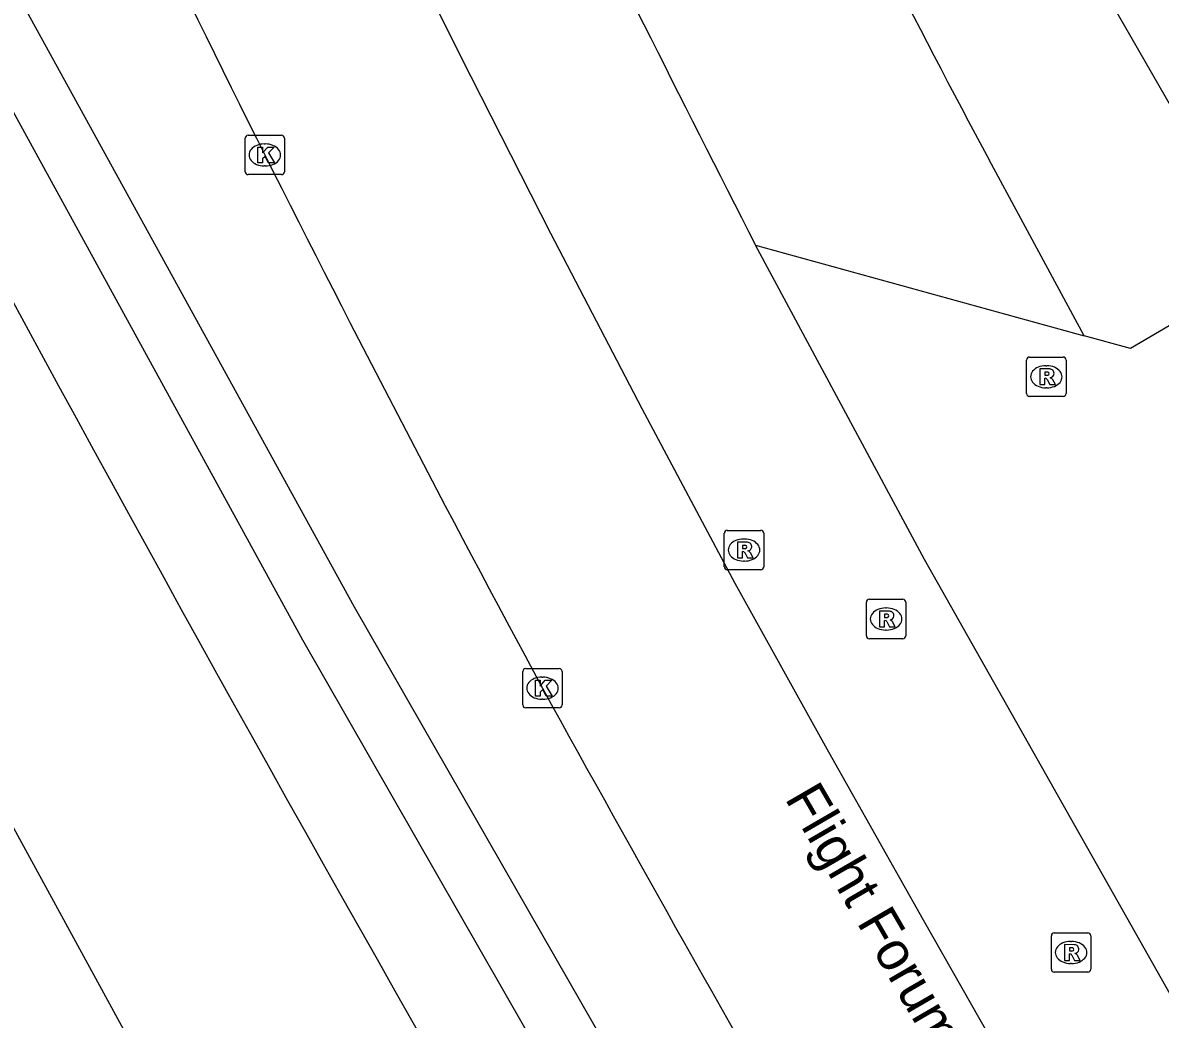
# Model space of a CAD drawing. Extents: x 155018 to 156648, y 383980 to 385733.
# Drawn here: x 155915.42 to 155944.32, y 384890.53 to 384915.84 of the extents above; entities that cross this region are included whole.
import ezdxf

# ---------------------------------------------------------------- set-up
doc = ezdxf.new("R2010")
doc.units = 0
for name, color, linetype in [('IMGEO_Greppel_droge_sloot', 7, 'Continuous'), ('IMGEO_Kolk', 7, 'Continuous'), ('IMGEO_Openbare_ruimte_label', 7, 'Continuous'), ('IMGEO_Parkeervlak_gesloten', 7, 'Continuous'), ('IMGEO_Rijbaan_lokaal_gesloten', 7, 'Continuous'), ('IMGEO_Rijbaan_lokaal_open', 7, 'Continuous'), ('IMGEO_Rijbaan_regionaal_gesloten', 7, 'Continuous'), ('IMGEO_Rioolput', 7, 'Continuous'), ('IMGEO_Voetpad_open', 7, 'Continuous')]:
    doc.layers.add(name, color=color, linetype=linetype)

msp = doc.modelspace()

# ---------------------------------------------------------------- linework, layer by layer
at = {"layer": 'IMGEO_Greppel_droge_sloot'}
for points in [[(155908.561, 384929.213), (155912.886, 384920.904), (155923.838, 384901.004), (155962.543, 384833.543)], [(155961.154, 384832.74), (155922.534, 384900.162), (155911.536, 384920.207), (155907.015, 384928.97)]]:
    msp.add_lwpolyline(points, dxfattribs=at)
at = {"layer": 'IMGEO_Kolk'}
for p, q in [((155921.065, 384912.059), (155921.065, 384912.911)), ((155921.14, 384912.985), (155921.992, 384912.985)), ((155922.066, 384912.911), (155922.066, 384912.059)), ((155921.553, 384912.765), (155921.578, 384912.765)), ((155921.992, 384911.985), (155921.14, 384911.985)), ((155921.576, 384912.205), (155921.551, 384912.205)), ((155928.119, 384898.515), (155928.119, 384899.367)), ((155928.194, 384899.441), (155929.046, 384899.441)), ((155928.607, 384899.221), (155928.632, 384899.221)), ((155929.12, 384899.367), (155929.12, 384898.515)), ((155928.63, 384898.661), (155928.605, 384898.661)), ((155929.046, 384898.441), (155928.194, 384898.441))]:
    msp.add_line(p, q, dxfattribs=at)
for points in [[(155921.065, 384912.059), (155921.065, 384912.911)], [(155921.14, 384912.985), (155921.992, 384912.985)], [(155922.066, 384912.911), (155922.066, 384912.059)], [(155921.386, 384912.685), (155921.509, 384912.685), (155921.509, 384912.534), (155921.639, 384912.685), (155921.803, 384912.685), (155921.657, 384912.534), (155921.81, 384912.285), (155921.658, 384912.285), (155921.573, 384912.449), (155921.509, 384912.382), (155921.509, 384912.285), (155921.386, 384912.285), (155921.386, 384912.685)], [(155921.992, 384911.985), (155921.14, 384911.985)], [(155928.119, 384898.515), (155928.119, 384899.367)], [(155928.194, 384899.441), (155929.046, 384899.441)], [(155929.12, 384899.367), (155929.12, 384898.515)], [(155928.44, 384899.141), (155928.563, 384899.141), (155928.563, 384898.99), (155928.693, 384899.141), (155928.857, 384899.141), (155928.711, 384898.99), (155928.864, 384898.741), (155928.712, 384898.741), (155928.627, 384898.905), (155928.563, 384898.838), (155928.563, 384898.741), (155928.44, 384898.741), (155928.44, 384899.141)], [(155929.046, 384898.441), (155928.194, 384898.441)]]:
    msp.add_lwpolyline(points, dxfattribs=at)
for centre, start, end in [((155921.142, 384912.909), 91.552, 178.448), ((155921.142, 384912.909), 91.552, 178.448), ((155921.99, 384912.909), 1.552, 88.448), ((155921.99, 384912.909), 1.552, 88.448), ((155921.142, 384912.061), 181.552, 268.448), ((155921.142, 384912.061), 181.552, 268.448), ((155921.99, 384912.061), 271.552, 358.448), ((155921.99, 384912.061), 271.552, 358.448), ((155928.196, 384899.365), 91.552, 178.448), ((155928.196, 384899.365), 91.552, 178.448), ((155929.044, 384899.365), 1.552, 88.448), ((155929.044, 384899.365), 1.552, 88.448), ((155928.196, 384898.517), 181.552, 268.448), ((155928.196, 384898.517), 181.552, 268.448), ((155929.044, 384898.517), 271.552, 358.448), ((155929.044, 384898.517), 271.552, 358.448)]:
    msp.add_arc(centre, 0.0765, start, end, dxfattribs=at)
for centre, major_axis, ratio, start_param, end_param in [((155921.552, 384912.485), (-0.387, 0.002), 0.722429, 4.712389, 7.853982), ((155921.577, 384912.485), (-0.39, 0.002), 0.717154, 1.570796, 4.712389), ((155928.606, 384898.941), (-0.387, 0.002), 0.722429, 4.712389, 7.853982), ((155928.631, 384898.941), (-0.39, 0.002), 0.717154, 1.570796, 4.712389)]:
    msp.add_ellipse(centre, major_axis=major_axis, ratio=ratio, start_param=start_param, end_param=end_param, dxfattribs=at)
at = {"layer": 'IMGEO_Parkeervlak_gesloten'}
msp.add_lwpolyline([(155970.829, 384923.546), (155969.356, 384924.492), (155968.552, 384925.897), (155973.194, 384928.631), (155956.893, 384956.764), (155938.438, 384946.207), (155928.999, 384940.799), (155945.318, 384912.45), (155950.245, 384915.182), (155951.149, 384913.415), (155950.99, 384911.918)], dxfattribs=at)
for centre, radius, start, end in [((156613.45, 385257.371), 773.079, 205.358475, 206.495062), ((156400.107, 385153.11), 535.632, 206.69467, 208.32823), ((156736.167, 385344.774), 922.442, 208.902362, 209.823666)]:
    msp.add_arc(centre, radius, start, end, dxfattribs=at)
at = {"layer": 'IMGEO_Rijbaan_lokaal_gesloten'}
for points in [[(155912.529, 384944.815), (155918.109, 384932.502), (155925.205, 384917.685), (155925.651, 384916.782), (155926.098, 384915.88), (155926.547, 384914.979), (155928.826, 384910.5), (155931.147, 384906.043), (155933.51, 384901.609), (155935.89, 384897.326), (155938.292, 384893.055), (155940.718, 384888.798), (155948.253, 384875.822), (155956.062, 384862.435), (155963.834, 384849.111), (155971.597, 384835.865), (155973.203, 384833.364), (155981.253, 384820.042)], [(155944.902, 384890.583), (155938.324, 384902.21), (155934.031, 384910.194)]]:
    msp.add_lwpolyline(points, dxfattribs=at)
msp.add_arc((156861.055, 385382.425), 1040.373, 205.611216, 206.994533, dxfattribs=at)
at = {"layer": 'IMGEO_Rijbaan_lokaal_open'}
for points in [[(155950.99, 384911.918), (155943.564, 384907.565), (155942.381, 384907.891)], [(155934.031, 384910.194), (155942.381, 384907.891)]]:
    msp.add_lwpolyline(points, dxfattribs=at)
at = {"layer": 'IMGEO_Rijbaan_regionaal_gesloten'}
msp.add_lwpolyline([(155894.98, 384933.155), (155898.732, 384925.896), (155902.596, 384918.444), (155920.302, 384886.009), (155931.668, 384866.172), (155968.307, 384802.15)], dxfattribs=at)
msp.add_arc((156792.642, 385383.905), 997.862, 206.71492, 210.115927, dxfattribs=at)
at = {"layer": 'IMGEO_Rioolput'}
for p, q in [((155940.997, 384907.35), (155941.849, 384907.35)), ((155940.922, 384906.424), (155940.922, 384907.276)), ((155941.41, 384907.13), (155941.435, 384907.13)), ((155941.923, 384907.276), (155941.923, 384906.424)), ((155941.433, 384906.57), (155941.408, 384906.57)), ((155941.849, 384906.35), (155940.997, 384906.35)), ((155933.241, 384902.024), (155933.241, 384902.876)), ((155933.316, 384902.95), (155934.168, 384902.95)), ((155933.729, 384902.73), (155933.754, 384902.73)), ((155934.242, 384902.876), (155934.242, 384902.024)), ((155933.752, 384902.17), (155933.727, 384902.17)), ((155934.168, 384901.95), (155933.316, 384901.95)), ((155936.851, 384900.272), (155936.851, 384901.124)), ((155936.926, 384901.198), (155937.778, 384901.198)), ((155937.339, 384900.978), (155937.364, 384900.978)), ((155937.852, 384901.124), (155937.852, 384900.272)), ((155937.362, 384900.418), (155937.337, 384900.418)), ((155937.778, 384900.198), (155936.926, 384900.198)), ((155941.551, 384891.802), (155941.551, 384892.654)), ((155941.626, 384892.728), (155942.478, 384892.728)), ((155942.552, 384892.654), (155942.552, 384891.802)), ((155942.039, 384892.508), (155942.064, 384892.508)), ((155942.478, 384891.728), (155941.626, 384891.728)), ((155942.062, 384891.948), (155942.037, 384891.948))]:
    msp.add_line(p, q, dxfattribs=at)
for points in [[(155940.997, 384907.35), (155941.849, 384907.35)], [(155940.922, 384906.424), (155940.922, 384907.276)], [(155941.511, 384907.048), (155941.259, 384907.05), (155941.259, 384906.65)], [(155941.923, 384907.276), (155941.923, 384906.424)], [(155941.259, 384906.65), (155941.383, 384906.65), (155941.383, 384906.812), (155941.394, 384906.812)], [(155941.437, 384906.969), (155941.383, 384906.969), (155941.383, 384906.888)], [(155941.383, 384906.888), (155941.435, 384906.888)], [(155941.441, 384906.783), (155941.512, 384906.65), (155941.652, 384906.65), (155941.587, 384906.776)], [(155941.849, 384906.35), (155940.997, 384906.35)], [(155933.241, 384902.024), (155933.241, 384902.876)], [(155933.316, 384902.95), (155934.168, 384902.95)], [(155934.242, 384902.876), (155934.242, 384902.024)], [(155933.83, 384902.648), (155933.578, 384902.65), (155933.578, 384902.25)], [(155933.578, 384902.25), (155933.702, 384902.25), (155933.702, 384902.412), (155933.713, 384902.412)], [(155933.756, 384902.569), (155933.702, 384902.569), (155933.702, 384902.488)], [(155933.702, 384902.488), (155933.754, 384902.488)], [(155933.76, 384902.383), (155933.831, 384902.25), (155933.971, 384902.25), (155933.906, 384902.376)], [(155934.168, 384901.95), (155933.316, 384901.95)], [(155936.851, 384900.272), (155936.851, 384901.124)], [(155936.926, 384901.198), (155937.778, 384901.198)], [(155937.852, 384901.124), (155937.852, 384900.272)], [(155937.44, 384900.896), (155937.188, 384900.898), (155937.188, 384900.498)], [(155937.188, 384900.498), (155937.312, 384900.498), (155937.312, 384900.66), (155937.323, 384900.66)], [(155937.366, 384900.817), (155937.312, 384900.817), (155937.312, 384900.736)], [(155937.312, 384900.736), (155937.364, 384900.736)], [(155937.37, 384900.631), (155937.441, 384900.498), (155937.581, 384900.498), (155937.516, 384900.624)], [(155937.778, 384900.198), (155936.926, 384900.198)], [(155941.551, 384891.802), (155941.551, 384892.654)], [(155941.626, 384892.728), (155942.478, 384892.728)], [(155942.552, 384892.654), (155942.552, 384891.802)], [(155942.14, 384892.426), (155941.888, 384892.428), (155941.888, 384892.028)], [(155942.066, 384892.347), (155942.012, 384892.347), (155942.012, 384892.266)], [(155941.888, 384892.028), (155942.012, 384892.028), (155942.012, 384892.19), (155942.023, 384892.19)], [(155942.012, 384892.266), (155942.064, 384892.266)], [(155942.07, 384892.161), (155942.141, 384892.028), (155942.281, 384892.028), (155942.216, 384892.154)], [(155942.478, 384891.728), (155941.626, 384891.728)]]:
    msp.add_lwpolyline(points, dxfattribs=at)
for centre, radius, start, end in [((155940.999, 384907.274), 0.0765, 91.552, 178.448), ((155940.999, 384907.274), 0.0765, 91.552, 178.448), ((155941.847, 384907.274), 0.0765, 1.552, 88.448), ((155941.847, 384907.274), 0.0765, 1.552, 88.448), ((155941.51, 384906.938), 0.109, 350.3612, 89.416), ((155941.393, 384906.759), 0.0533, 26.0293, 88.6989), ((155941.419, 384907.077), 0.19, 274.7715, 282.9687), ((155941.443, 384906.873), 0.0964, 77.0061, 93.1865), ((155941.457, 384906.93), 0.0378, 276.6634, 79.6772), ((155941.508, 384906.938), 0.112, 277.5842, 350.9817), ((155941.492, 384906.723), 0.108, 29.5134, 73.7905), ((155940.999, 384906.426), 0.0765, 181.552, 268.448), ((155940.999, 384906.426), 0.0765, 181.552, 268.448), ((155941.847, 384906.426), 0.0765, 271.552, 358.448), ((155941.847, 384906.426), 0.0765, 271.552, 358.448), ((155933.318, 384902.874), 0.0765, 91.552, 178.448), ((155933.318, 384902.874), 0.0765, 91.552, 178.448), ((155934.166, 384902.874), 0.0765, 1.552, 88.448), ((155934.166, 384902.874), 0.0765, 1.552, 88.448), ((155933.712, 384902.359), 0.0533, 26.0293, 88.6989), ((155933.738, 384902.677), 0.19, 274.7715, 282.9687), ((155933.762, 384902.473), 0.0964, 77.0061, 93.1865), ((155933.776, 384902.53), 0.0378, 276.6634, 79.6772), ((155933.829, 384902.538), 0.109, 350.3612, 89.416), ((155933.827, 384902.538), 0.112, 277.5842, 350.9817), ((155933.811, 384902.323), 0.108, 29.5134, 73.7905), ((155933.318, 384902.026), 0.0765, 181.552, 268.448), ((155933.318, 384902.026), 0.0765, 181.552, 268.448), ((155934.166, 384902.026), 0.0765, 271.552, 358.448), ((155934.166, 384902.026), 0.0765, 271.552, 358.448), ((155936.928, 384901.122), 0.0765, 91.552, 178.448), ((155936.928, 384901.122), 0.0765, 91.552, 178.448), ((155937.776, 384901.122), 0.0765, 1.552, 88.448), ((155937.776, 384901.122), 0.0765, 1.552, 88.448), ((155937.322, 384900.607), 0.0533, 26.0293, 88.6989), ((155937.348, 384900.925), 0.19, 274.7715, 282.9687), ((155937.372, 384900.721), 0.0964, 77.0061, 93.1865), ((155937.386, 384900.778), 0.0378, 276.6634, 79.6772), ((155937.439, 384900.786), 0.109, 350.3612, 89.416), ((155937.437, 384900.786), 0.112, 277.5842, 350.9817), ((155937.421, 384900.571), 0.108, 29.5134, 73.7905), ((155936.928, 384900.274), 0.0765, 181.552, 268.448), ((155936.928, 384900.274), 0.0765, 181.552, 268.448), ((155937.776, 384900.274), 0.0765, 271.552, 358.448), ((155937.776, 384900.274), 0.0765, 271.552, 358.448), ((155941.628, 384892.652), 0.0765, 91.552, 178.448), ((155941.628, 384892.652), 0.0765, 91.552, 178.448), ((155942.476, 384892.652), 0.0765, 1.552, 88.448), ((155942.476, 384892.652), 0.0765, 1.552, 88.448), ((155942.072, 384892.251), 0.0964, 77.0061, 93.1865), ((155942.086, 384892.308), 0.0378, 276.6634, 79.6772), ((155942.139, 384892.316), 0.109, 350.3612, 89.416), ((155942.137, 384892.316), 0.112, 277.5842, 350.9817), ((155942.022, 384892.137), 0.0533, 26.0293, 88.6989), ((155942.048, 384892.455), 0.19, 274.7715, 282.9687), ((155942.121, 384892.101), 0.108, 29.5134, 73.7905), ((155941.628, 384891.804), 0.0765, 181.552, 268.448), ((155941.628, 384891.804), 0.0765, 181.552, 268.448), ((155942.476, 384891.804), 0.0765, 271.552, 358.448), ((155942.476, 384891.804), 0.0765, 271.552, 358.448)]:
    msp.add_arc(centre, radius, start, end, dxfattribs=at)
for centre, major_axis, ratio, start_param, end_param in [((155941.409, 384906.85), (-0.387, 0.002), 0.722429, 4.712389, 7.853982), ((155941.434, 384906.85), (-0.39, 0.002), 0.717154, 1.570796, 4.712389), ((155933.728, 384902.45), (-0.387, 0.002), 0.722429, 4.712389, 7.853982), ((155933.753, 384902.45), (-0.39, 0.002), 0.717154, 1.570796, 4.712389), ((155937.338, 384900.698), (-0.387, 0.002), 0.722429, 4.712389, 7.853982), ((155937.363, 384900.698), (-0.39, 0.002), 0.717154, 1.570796, 4.712389), ((155942.038, 384892.228), (-0.387, 0.002), 0.722429, 4.712389, 7.853982), ((155942.063, 384892.228), (-0.39, 0.002), 0.717154, 1.570796, 4.712389)]:
    msp.add_ellipse(centre, major_axis=major_axis, ratio=ratio, start_param=start_param, end_param=end_param, dxfattribs=at)
at = {"layer": 'IMGEO_Voetpad_open'}
msp.add_lwpolyline([(155942.381, 384907.891), (155939.967, 384912.358)], dxfattribs=at)
msp.add_arc((156207.485, 385055.285), 303.305, 205.84921, 208.11435, dxfattribs=at)

# ---------------------------------------------------------------- texts
at = {"layer": 'IMGEO_Openbare_ruimte_label'}
msp.add_text('Flight Forum', height=1, rotation=300.1286, dxfattribs=at).set_placement((155934.764, 384896.144))

doc.saveas('drawing.dxf')
